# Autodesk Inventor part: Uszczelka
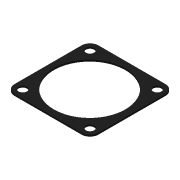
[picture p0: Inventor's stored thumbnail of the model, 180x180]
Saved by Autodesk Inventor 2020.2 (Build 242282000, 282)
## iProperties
Created: 2006-01
Part Number: Uszczelka
Document SubType Name: Modeling
Designer: F.Stasiak
Density: 1 g/cm^3
Material: Ogólny
Appearance: Tworzywo sztuczne (szare)
Manager: www.cadconsulting.pl
Company: Fabian Stasiak CAD Consulting
Author: F.Stasiak
Subject: Zbiór ćwiczeń. Autodesk Inventor 2020. Kurs podstawowy
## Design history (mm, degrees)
sketch "Szkic1"
  geometry: L1 (0, 40)-(0, -40) reference; L2 (-10, 50)-(-90, 50) reference; L3 (-100, 40)-(-100, -40) reference; L4 (-90, -50)-(-10, -50) reference; C1 r 37.5 at (-50.488, 0) reference; C2 r 3.458 at (-90, -40) reference; C3 r 3.458 at (-10, 40) reference; C4 r 3.458 at (-10, -40) reference; C5 r 3.458 at (-90, 40) reference; C6 r 42.5 at (-50.488, 0); C7 r 5 at (-90, 40); C8 r 5 at (-10, 40); C9 r 5 at (-10, -40); C10 r 5 at (-90, -40); A1 r 10 centre (-10, -40) between (-10, -50) and (0, -40) reference; A2 r 10 centre (-10, 40) between (0, 40) and (-10, 50) reference; A3 r 10 centre (-90, 40) between (-90, 50) and (-100, 40) reference; A4 r 10 centre (-90, -40) between (-100, -40) and (-90, -50) reference
  constraints: 5 centre point, 3 equal radius
  dimensions: "d0" = 85 diameter of C6; "d1" = 10 diameter of C7
extrude "Wyciągnięcie proste1" new body sketch "Szkic1" distance "d2" = 2; taper "d3" = 0 deg
node "Bryła1"
node "Korpusy bryłowe"
node "Korpusy powierzchniowe"
node "Odniesienie1"
